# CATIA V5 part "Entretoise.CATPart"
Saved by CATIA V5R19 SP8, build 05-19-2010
Part number: Entretoise
Revision: ANY
Definition: UNKNOWN
Nomenclature: Entretoise
Source: Unknown
Bounding box of the stored display mesh (mm): x -4.99 to 4.99, y 0 to 16.75, z -5 to 5
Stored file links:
  D:\Documents\1_Travail\1 - ac-limoges.fr\OneDrive - ac-limoges.fr\STI2D_Turgot\2 -2I2D\3_SEQUENCE_Serre_Connectée\3- Spécificités\ITEC\EC 3 Ouverture automatique\Simulation  Ouverture Automatique\Entretoise.CATPart
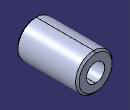
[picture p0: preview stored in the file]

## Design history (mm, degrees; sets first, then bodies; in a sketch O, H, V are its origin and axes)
Body1 "NONE" (main body)
  Solid1: solid without history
